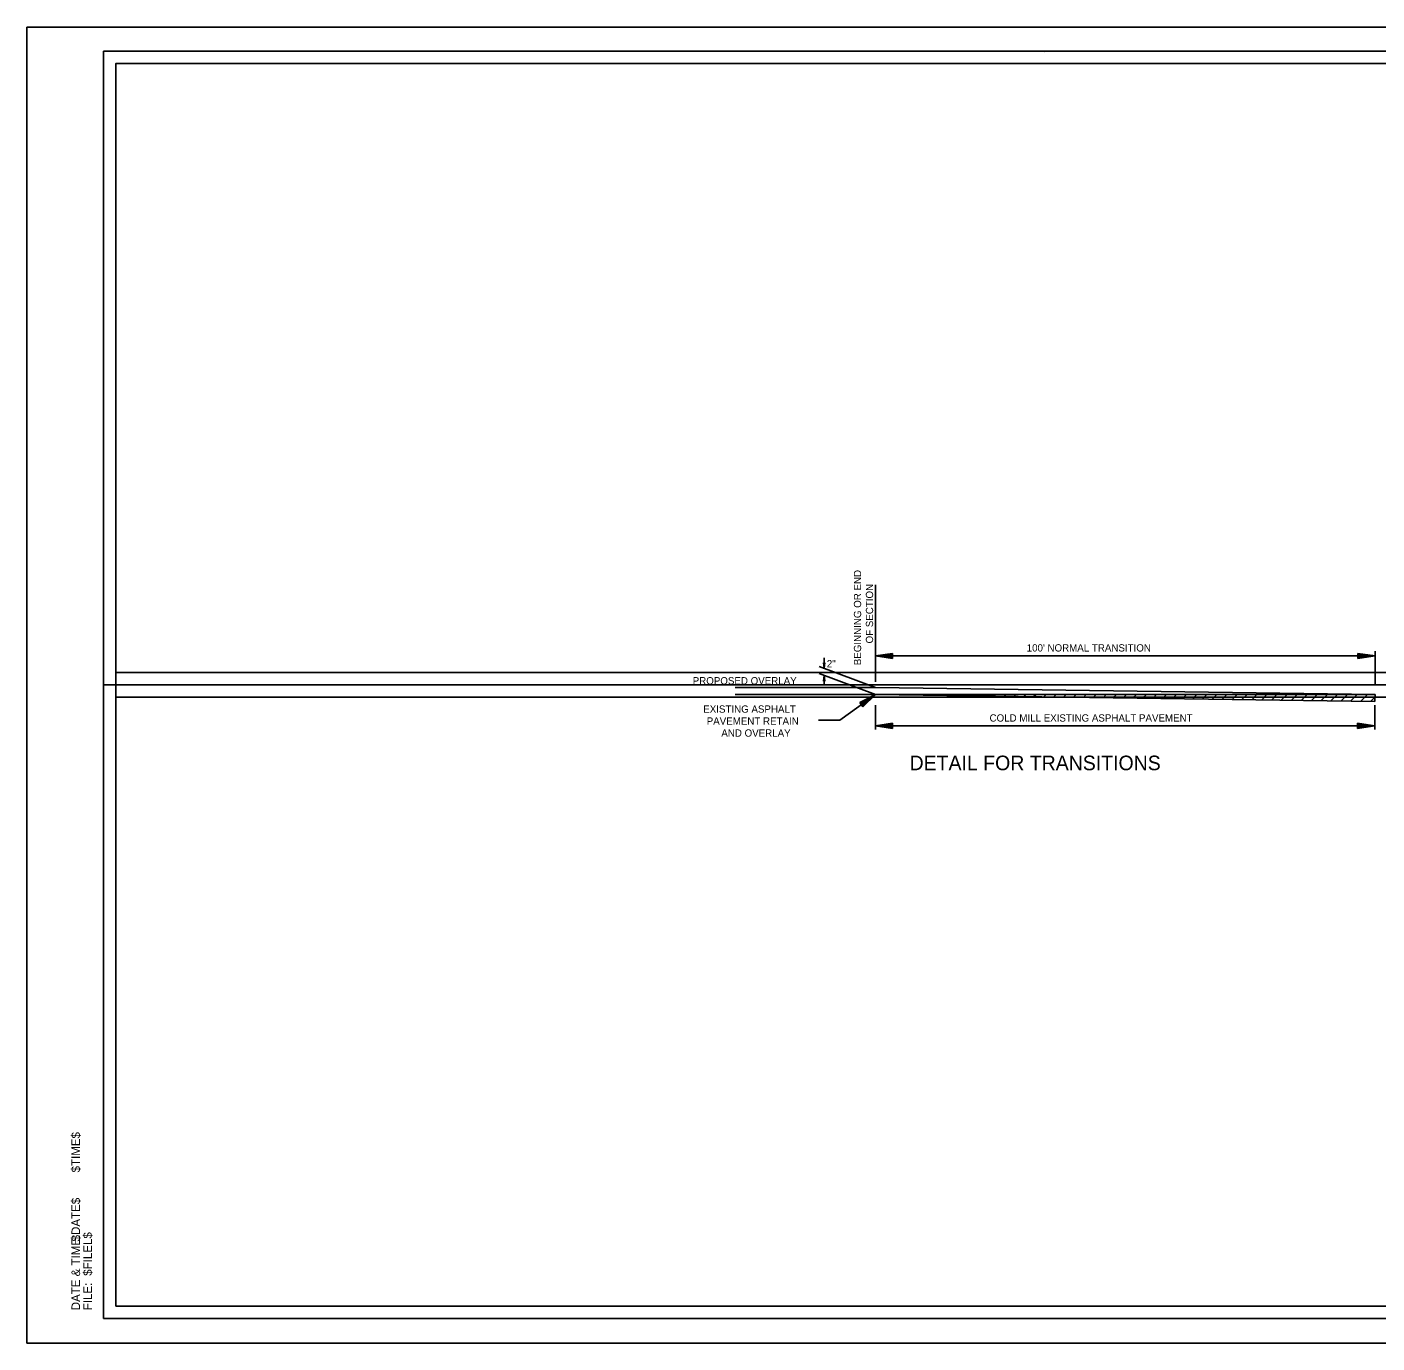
# Model space of a CAD drawing. Extents: x 1369904 to 1370238, y 380119 to 380332.
# Drawn here: x 1369904.4 to 1370123.3, y 380118.8 to 380332.1 of the extents above; entities that cross this region are included whole.
import ezdxf

# ---------------------------------------------------------------- set-up
doc = ezdxf.new("R2010")
doc.units = 0
for name, color, linetype in [('Default', 7, 'Continuous'), ('R_Border', 7, 'Continuous'), ('R_Border Notes', 7, 'Continuous'), ('R_Border Plan-Plan', 7, 'Continuous'), ('R_No Plot', 7, 'Continuous')]:
    doc.layers.add(name, color=color, linetype=linetype)

msp = doc.modelspace()

# ---------------------------------------------------------------- linework, layer by layer
at = {"layer": 'Default'}
for p, q in [((1370041.93, 380225.97), (1370041.93, 380241.69)), ((1370122.96, 380225.36), (1370122.96, 380230.95)), ((1370033.5, 380229.08), (1370033.63, 380228.2)), ((1370033.5, 380229.08), (1370033.63, 380228.33)), ((1370033.76, 380229.08), (1370033.5, 380229.08)), ((1370033.54, 380229.08), (1370033.63, 380228.51)), ((1370033.54, 380229.08), (1370033.63, 380228.64)), ((1370033.58, 380229.08), (1370033.63, 380228.81)), ((1370033.58, 380229.08), (1370033.63, 380228.94)), ((1370033.63, 380228.2), (1370033.63, 380229.86)), ((1370033.76, 380229.08), (1370033.63, 380228.2)), ((1370033.67, 380229.08), (1370033.63, 380228.81)), ((1370033.72, 380229.08), (1370033.63, 380228.51)), ((1370033.72, 380229.08), (1370033.63, 380228.33)), ((1370033.67, 380229.08), (1370033.63, 380228.64)), ((1370033.63, 380229.08), (1370033.63, 380228.94)), ((1370044.71, 380230.59), (1370041.93, 380230.17)), ((1370041.93, 380230.17), (1370122.96, 380230.17)), ((1370044.71, 380229.76), (1370041.93, 380230.17)), ((1370044.71, 380230.52), (1370042.4, 380230.17)), ((1370044.71, 380229.82), (1370042.4, 380230.17)), ((1370044.71, 380230.45), (1370042.88, 380230.17)), ((1370044.71, 380229.89), (1370042.88, 380230.17)), ((1370044.71, 380230.38), (1370043.34, 380230.17)), ((1370044.71, 380229.97), (1370043.34, 380230.17)), ((1370044.71, 380230.31), (1370043.81, 380230.17)), ((1370044.71, 380230.04), (1370043.81, 380230.17)), ((1370044.71, 380230.23), (1370044.27, 380230.17)), ((1370044.71, 380230.1), (1370044.27, 380230.17)), ((1370044.71, 380229.76), (1370044.71, 380230.59)), ((1370120.18, 380230.58), (1370122.96, 380230.17)), ((1370120.18, 380230.58), (1370120.18, 380229.75)), ((1370120.18, 380230.52), (1370122.49, 380230.17)), ((1370120.18, 380230.44), (1370122.02, 380230.17)), ((1370120.18, 380230.36), (1370121.55, 380230.17)), ((1370120.18, 380230.3), (1370121.08, 380230.17)), ((1370120.18, 380230.23), (1370120.62, 380230.17)), ((1370120.18, 380229.75), (1370122.96, 380230.17)), ((1370120.18, 380230.03), (1370121.08, 380230.17)), ((1370120.18, 380229.89), (1370122.02, 380230.17)), ((1370120.18, 380229.81), (1370122.49, 380230.17)), ((1370120.18, 380229.96), (1370121.55, 380230.17)), ((1370120.18, 380230.1), (1370120.62, 380230.17)), ((1370041.93, 380225.05), (1370032.8, 380228.46)), ((1370041.93, 380223.92), (1370032.8, 380227.33)), ((1370033.5, 380226.1), (1370033.63, 380227.02)), ((1370033.5, 380226.1), (1370033.63, 380226.89)), ((1370033.54, 380226.1), (1370033.63, 380226.71)), ((1370033.54, 380226.1), (1370033.63, 380226.58)), ((1370033.76, 380226.1), (1370033.63, 380227.02)), ((1370033.63, 380225.36), (1370033.63, 380227.02)), ((1370033.72, 380226.1), (1370033.63, 380226.89)), ((1370033.72, 380226.1), (1370033.63, 380226.71)), ((1370033.67, 380226.1), (1370033.63, 380226.58)), ((1370019.2, 380225.05), (1370041.93, 380225.05)), ((1370033.5, 380226.1), (1370033.76, 380226.1)), ((1370033.58, 380226.1), (1370033.63, 380226.41)), ((1370033.58, 380226.1), (1370033.63, 380226.23)), ((1370033.67, 380226.1), (1370033.63, 380226.41)), ((1370033.63, 380226.1), (1370033.63, 380226.23)), ((1370122.96, 380223.92), (1370041.93, 380225.05)), ((1370019.2, 380223.91), (1370122.96, 380223.91)), ((1370036.17, 380219.76), (1370041.93, 380223.92)), ((1370039.44, 380222.63), (1370041.93, 380223.92)), ((1370039.44, 380222.63), (1370039.92, 380221.95)), ((1370039.48, 380222.57), (1370041.56, 380223.64)), ((1370039.52, 380222.52), (1370041.17, 380223.36)), ((1370039.56, 380222.46), (1370040.8, 380223.1)), ((1370039.6, 380222.4), (1370040.41, 380222.82)), ((1370039.64, 380222.35), (1370040.04, 380222.55)), ((1370039.72, 380222.24), (1370040.04, 380222.55)), ((1370039.77, 380222.17), (1370040.41, 380222.82)), ((1370039.8, 380222.12), (1370040.8, 380223.1)), ((1370039.85, 380222.06), (1370041.17, 380223.36)), ((1370039.89, 380222.01), (1370041.56, 380223.64)), ((1370039.92, 380221.95), (1370041.93, 380223.92)), ((1370122.92, 380222.78), (1370041.93, 380223.92)), ((1370041.93, 380218.27), (1370041.93, 380222.21)), ((1370045.13, 380223.87), (1370045.17, 380223.92)), ((1370046.72, 380223.85), (1370046.79, 380223.92)), ((1370048.32, 380223.83), (1370048.45, 380223.92)), ((1370049.95, 380223.8), (1370050.07, 380223.92)), ((1370051.55, 380223.78), (1370051.69, 380223.92)), ((1370053.15, 380223.76), (1370053.3, 380223.92)), ((1370054.75, 380223.74), (1370054.92, 380223.92)), ((1370056.38, 380223.71), (1370056.58, 380223.92)), ((1370057.98, 380223.69), (1370058.2, 380223.92)), ((1370059.61, 380223.67), (1370059.82, 380223.92)), ((1370061.17, 380223.64), (1370061.44, 380223.92)), ((1370062.81, 380223.62), (1370063.1, 380223.92)), ((1370064.4, 380223.6), (1370064.72, 380223.92)), ((1370066.04, 380223.58), (1370066.34, 380223.92)), ((1370067.59, 380223.55), (1370068, 380223.92)), ((1370069.23, 380223.53), (1370069.62, 380223.92)), ((1370070.83, 380223.51), (1370071.23, 380223.92)), ((1370072.42, 380223.48), (1370072.85, 380223.91)), ((1370074.02, 380223.46), (1370074.51, 380223.92)), ((1370075.66, 380223.44), (1370076.13, 380223.92)), ((1370077.25, 380223.42), (1370077.75, 380223.92)), ((1370078.85, 380223.4), (1370079.36, 380223.92)), ((1370080.44, 380223.37), (1370081.02, 380223.92)), ((1370082.08, 380223.35), (1370082.64, 380223.92)), ((1370083.63, 380223.33), (1370084.26, 380223.92)), ((1370085.27, 380223.31), (1370085.88, 380223.92)), ((1370086.91, 380223.28), (1370087.5, 380223.92)), ((1370088.5, 380223.26), (1370089.16, 380223.92)), ((1370090.1, 380223.24), (1370090.78, 380223.92)), ((1370091.7, 380223.22), (1370092.4, 380223.92)), ((1370093.34, 380223.19), (1370094.06, 380223.92)), ((1370094.93, 380223.17), (1370095.68, 380223.92)), ((1370096.53, 380223.15), (1370097.29, 380223.92)), ((1370098.12, 380223.12), (1370098.91, 380223.92)), ((1370099.76, 380223.1), (1370100.57, 380223.92)), ((1370101.31, 380223.08), (1370102.19, 380223.92)), ((1370102.95, 380223.06), (1370103.81, 380223.92)), ((1370104.55, 380223.03), (1370105.42, 380223.92)), ((1370106.18, 380223.01), (1370107.04, 380223.92)), ((1370107.74, 380222.99), (1370108.71, 380223.92)), ((1370109.37, 380222.97), (1370110.32, 380223.92)), ((1370110.98, 380222.95), (1370111.94, 380223.92)), ((1370112.57, 380222.92), (1370113.56, 380223.92)), ((1370114.16, 380222.9), (1370115.22, 380223.92)), ((1370115.8, 380222.88), (1370116.84, 380223.92)), ((1370117.4, 380222.85), (1370118.46, 380223.92)), ((1370118.99, 380222.83), (1370120.07, 380223.92)), ((1370120.59, 380222.81), (1370121.74, 380223.92)), ((1370122.22, 380222.79), (1370122.94, 380223.5)), ((1370122.96, 380223.92), (1370122.92, 380222.78)), ((1370122.92, 380218.27), (1370122.92, 380222.21)), ((1370032.71, 380219.76), (1370036.17, 380219.76)), ((1370044.71, 380219.26), (1370041.93, 380218.84)), ((1370042.81, 380218.97), (1370041.93, 380218.84)), ((1370122.92, 380218.84), (1370041.93, 380218.84)), ((1370042.81, 380218.71), (1370041.93, 380218.84)), ((1370044.71, 380218.43), (1370041.93, 380218.84)), ((1370042.81, 380218.97), (1370042.07, 380218.84)), ((1370042.81, 380218.76), (1370042.07, 380218.84)), ((1370042.81, 380218.93), (1370042.24, 380218.84)), ((1370042.81, 380218.76), (1370042.24, 380218.84)), ((1370042.81, 380218.93), (1370042.37, 380218.84)), ((1370042.81, 380218.8), (1370042.37, 380218.84)), ((1370044.71, 380219.2), (1370042.4, 380218.84)), ((1370044.71, 380218.5), (1370042.4, 380218.84)), ((1370042.81, 380218.88), (1370042.55, 380218.84)), ((1370042.81, 380218.8), (1370042.55, 380218.84)), ((1370042.81, 380218.88), (1370042.68, 380218.84)), ((1370042.81, 380218.84), (1370042.68, 380218.84)), ((1370042.81, 380218.71), (1370042.81, 380218.97)), ((1370044.71, 380219.13), (1370042.88, 380218.84)), ((1370044.71, 380218.57), (1370042.88, 380218.84)), ((1370044.71, 380219.05), (1370043.34, 380218.84)), ((1370044.71, 380218.64), (1370043.34, 380218.84)), ((1370044.71, 380218.99), (1370043.81, 380218.84)), ((1370044.71, 380218.71), (1370043.81, 380218.84)), ((1370044.71, 380218.91), (1370044.27, 380218.84)), ((1370044.71, 380218.78), (1370044.27, 380218.84)), ((1370044.71, 380218.43), (1370044.71, 380219.26)), ((1370120.13, 380219.26), (1370122.92, 380218.84)), ((1370120.13, 380219.26), (1370120.13, 380218.42)), ((1370120.13, 380219.19), (1370122.44, 380218.84)), ((1370120.13, 380219.12), (1370121.97, 380218.84)), ((1370120.13, 380219.04), (1370121.51, 380218.84)), ((1370120.13, 380218.98), (1370121.03, 380218.84)), ((1370120.13, 380218.91), (1370120.57, 380218.84)), ((1370120.13, 380218.42), (1370122.92, 380218.84)), ((1370120.13, 380218.7), (1370121.03, 380218.84)), ((1370120.13, 380218.56), (1370121.97, 380218.84)), ((1370120.13, 380218.49), (1370122.44, 380218.84)), ((1370120.13, 380218.63), (1370121.51, 380218.84)), ((1370120.13, 380218.77), (1370120.57, 380218.84))]:
    msp.add_line(p, q, dxfattribs=at)
at = {"layer": 'R_Border'}
for p, q in [((1369916.79, 380328.24), (1370232.97, 380328.24)), ((1369916.79, 380122.78), (1369916.79, 380328.24)), ((1370069.31, 380327.98), (1370069.31, 380327.98)), ((1370069.31, 380327.98), (1370069.31, 380327.98)), ((1369916.79, 380122.78), (1369916.79, 380122.78)), ((1370232.97, 380122.78), (1369916.79, 380122.78))]:
    msp.add_line(p, q, dxfattribs=at)
at = {"layer": 'R_Border Plan-Plan'}
msp.add_line((1369916.79, 380225.51), (1370232.97, 380225.51), dxfattribs=at)
at = {"layer": 'R_No Plot'}
for points in [[(1369904.38, 380332.13), (1370237.72, 380332.13), (1370237.72, 380118.79), (1369904.38, 380118.79)], [(1370230.97, 380227.51), (1369918.79, 380227.51), (1369918.79, 380326.24), (1370168.33, 380326.24), (1370168.33, 380316.36), (1370185.87, 380316.36), (1370209.97, 380316.36), (1370209.97, 380294.02), (1370230.97, 380294.02)], [(1369918.79, 380326.24), (1370168.33, 380326.24), (1370168.33, 380316.36), (1370185.87, 380316.36), (1370209.97, 380316.36), (1370209.97, 380294.02), (1370230.97, 380294.02), (1370230.97, 380124.78), (1369918.79, 380124.78)], [(1369918.79, 380223.51), (1370230.97, 380223.51), (1370230.97, 380124.78), (1369918.79, 380124.78)]]:
    msp.add_lwpolyline(points, close=True, dxfattribs=at)

# ---------------------------------------------------------------- texts
at = {"layer": 'Default'}
for s, height, rotation, p in [('BEGINNING OR END', 1.1812, 90, (1370039.63, 380228.67)), ('OF SECTION', 1.181, 90, (1370041.57, 380232.2)), ('2"', 1.181, 360, (1370034.06, 380228.32))]:
    msp.add_text(s, height=height, rotation=rotation, dxfattribs=at).set_placement(p)
for s, height, p in [("100' NORMAL TRANSITION", 1.1812, (1370066.47, 380230.89)), ('PROPOSED OVERLAY', 1.1812, (1370012.32, 380225.56)), ('EXISTING ASPHALT', 1.1812, (1370014.03, 380220.97)), ('PAVEMENT RETAIN', 1.1812, (1370014.59, 380219.03)), ('COLD MILL EXISTING ASPHALT PAVEMENT', 1.1812, (1370060.45, 380219.53)), ('AND OVERLAY', 1.1812, (1370016.96, 380217.09)), ('DETAIL FOR TRANSITIONS', 2.3625, (1370047.48, 380211.65))]:
    msp.add_text(s, height=height, dxfattribs=at).set_placement(p)
at = {"layer": 'R_Border Notes'}
for s, height, p in [('$TIME$', 1.397, (1369912.99, 380146.45)), ('$DATE$', 1.397, (1369912.99, 380135.27)), ('DATE & TIME:', 1.3968, (1369912.99, 380124.1)), ('$FILEL$', 1.397, (1369914.91, 380129.69)), ('FILE: ', 1.397, (1369914.91, 380124.1))]:
    msp.add_text(s, height=height, rotation=90, dxfattribs=at).set_placement(p)

doc.saveas('drawing.dxf')
